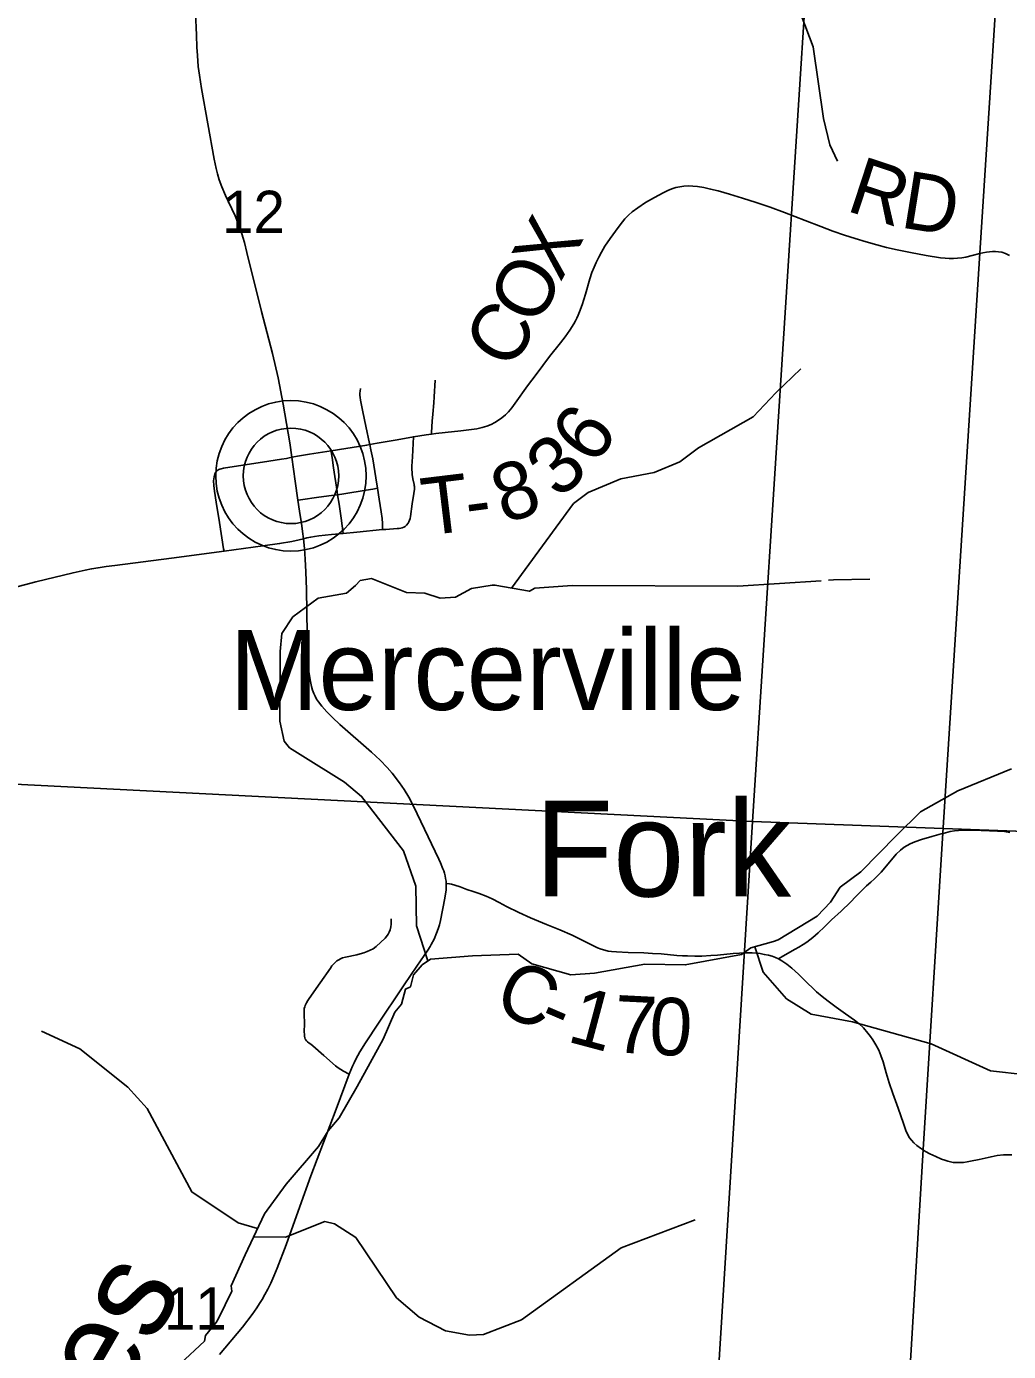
# Model space of a CAD drawing. Extents: x 0 to 34, y 0 to 22.
# Drawn here: x 27.638 to 28.609, y 18.925 to 20.235 of the extents above; entities that cross this region are included whole.
import ezdxf

# ---------------------------------------------------------------- set-up
doc = ezdxf.new("R2010")
doc.units = 0
for name, color, linetype in [('GM_X_County_Road', 7, 'Continuous'), ('GM_X_County_Road_Text', 7, 'Continuous'), ('GM_X_County_Text', 7, 'Continuous'), ('GM_X_Minor_River', 7, 'Continuous'), ('GM_X_Minor_River_Text', 7, 'Continuous'), ('GM_X_Section', 7, 'Continuous'), ('GM_X_Section_Text', 7, 'Continuous'), ('GM_X_State_Route', 7, 'Continuous'), ('GM_X_Township_Road', 7, 'Continuous'), ('GM_X_Township_Road_Text', 7, 'Continuous'), ('GM_X_Unincorporated', 7, 'Continuous'), ('GM_X_Unincorporated_Location', 7, 'Continuous'), ('GM_X_Unincorporated_Text', 7, 'Continuous')]:
    doc.layers.add(name, color=color, linetype=linetype)

msp = doc.modelspace()

# ---------------------------------------------------------------- linework, layer by layer
at = {"layer": 'GM_X_County_Road'}
for points in [[(27.5864, 19.6658), (27.5873, 19.6662), (27.5943, 19.6692), (27.6015, 19.6721), (27.6074, 19.6742), (27.613, 19.6762), (27.6189, 19.678), (27.6247, 19.6797), (27.647, 19.6855), (27.6839, 19.6946), (27.69, 19.696), (27.696, 19.6973), (27.7022, 19.6984), (27.7087, 19.6996), (27.7166, 19.7007), (27.7254, 19.7019), (27.7813, 19.7089), (27.8333, 19.7159), (27.8717, 19.7211), (27.8883, 19.7235), (27.9005, 19.7256), (27.9076, 19.727), (27.9119, 19.7281)], [(28.0531, 19.3873), (28.0564, 19.3871), (28.0584, 19.3868), (28.0615, 19.3859), (28.0668, 19.384), (28.0736, 19.3816), (28.0796, 19.3796), (28.0858, 19.3775), (28.0925, 19.375), (28.0985, 19.3723), (28.1056, 19.3686), (28.1128, 19.3648), (28.1249, 19.3588), (28.1364, 19.3534), (28.1522, 19.3469), (28.1656, 19.3415), (28.1775, 19.3363), (28.1888, 19.3309), (28.2028, 19.3237), (28.2063, 19.3224), (28.2099, 19.3214), (28.2132, 19.3207), (28.2166, 19.3203), (28.2215, 19.3198), (28.233, 19.3192), (28.2487, 19.3188), (28.2571, 19.3184), (28.2657, 19.3178), (28.2811, 19.3164), (28.2867, 19.316), (28.2917, 19.3158), (28.2991, 19.3157), (28.306, 19.3157), (28.3147, 19.3161), (28.3215, 19.3166), (28.3368, 19.3181), (28.3431, 19.3187), (28.3492, 19.3189), (28.3524, 19.319), (28.3556, 19.3188), (28.3596, 19.3185), (28.3637, 19.3181), (28.3676, 19.3174), (28.372, 19.3165), (28.3755, 19.3156), (28.3788, 19.3143), (28.3818, 19.313), (28.385, 19.3111), (28.3901, 19.3077), (28.3951, 19.3037), (28.4014, 19.2979), (28.4115, 19.2878), (28.4147, 19.2848), (28.4192, 19.2805), (28.4249, 19.2757), (28.4308, 19.2711), (28.4389, 19.2652), (28.4482, 19.2587), (28.457, 19.2525), (28.4617, 19.2486), (28.4657, 19.2448), (28.4701, 19.2396), (28.4727, 19.2363), (28.4752, 19.2328), (28.4781, 19.228), (28.481, 19.2226), (28.483, 19.2175), (28.4852, 19.2111), (28.4882, 19.2004), (28.4913, 19.1905), (28.4949, 19.1798), (28.5002, 19.1652), (28.5053, 19.1502), (28.5078, 19.1433), (28.5094, 19.1396), (28.5113, 19.1361), (28.5133, 19.1337), (28.5156, 19.1312), (28.5186, 19.1284), (28.5222, 19.1257), (28.5251, 19.1239)], [(28.5251, 19.1239), (28.5273, 19.1226), (28.5316, 19.1203), (28.5373, 19.1176), (28.543, 19.115), (28.5462, 19.1138), (28.5493, 19.1128), (28.5518, 19.1123), (28.5545, 19.1118), (28.5574, 19.1116), (28.5605, 19.1116), (28.5649, 19.1118), (28.5685, 19.1123), (28.5717, 19.1128), (28.5802, 19.1147), (28.5921, 19.1174), (28.5982, 19.1185), (28.6043, 19.1192), (28.6084, 19.1193), (28.6127, 19.1191)]]:
    msp.add_lwpolyline(points, dxfattribs=at)
at = {"layer": 'GM_X_County_Text'}
for points in [[(28.4159, 17.3358), (28.4427, 17.7695), (28.4677, 18.1732), (28.5249, 19.1245), (28.5443, 19.4375), (28.5808, 20.0106), (28.6062, 20.4055), (27.8401, 20.4449), (27.0539, 20.4845), (26.781, 20.4973), (26.0533, 20.5337), (24.4417, 20.6174), (23.8372, 20.6485), (23.8372, 14.4177)], [(29.547, 20.3639), (28.6062, 20.4055), (28.5808, 20.0106), (28.5443, 19.4375), (28.5249, 19.1245), (28.4677, 18.1732), (28.4427, 17.7695), (28.4159, 17.3358)]]:
    msp.add_lwpolyline(points, dxfattribs=at)
at = {"layer": 'GM_X_Minor_River'}
for points in [[(28.2827, 20.3892), (28.3446, 20.3542), (28.3707, 20.3061), (28.396, 20.2679), (28.4161, 20.2145), (28.4264, 20.1435), (28.4326, 20.1177), (28.4403, 20.1015)], [(28.1176, 19.6794), (28.1789, 19.763), (28.1935, 19.7739), (28.2257, 19.7873), (28.2588, 19.7938), (28.2841, 19.8044), (28.3026, 19.8182), (28.3568, 19.8488), (28.3791, 19.8724), (28.404, 19.8963)], [(28.0348, 19.311), (28.0237, 19.3457), (28.023, 19.3848), (28.0108, 19.4198), (27.9694, 19.4735), (27.9524, 19.4877), (27.9086, 19.5149), (27.8982, 19.5217), (27.8928, 19.528), (27.8885, 19.5478), (27.8887, 19.6169), (27.8903, 19.6347), (27.9014, 19.6511), (27.9265, 19.6696), (27.9543, 19.6745), (27.9632, 19.6821), (27.9679, 19.6869), (27.9793, 19.6888), (28.0137, 19.6752), (28.0318, 19.6743), (28.0471, 19.6696), (28.0623, 19.6706), (28.078, 19.6792), (28.0985, 19.6824), (28.1016, 19.6823)], [(28.4239, 19.6867), (28.3416, 19.6814), (28.1775, 19.6821), (28.1408, 19.6795), (28.1354, 19.6763), (28.1012, 19.6823)], [(28.472, 19.6883), (28.4363, 19.6875), (28.4313, 19.6872)], [(27.7898, 18.9125), (27.8139, 18.9349), (27.8151, 18.9406), (27.8256, 18.9536), (27.8279, 18.9574), (27.8411, 18.9844), (27.8403, 18.9897), (27.8543, 19.0202), (27.8732, 19.0609), (27.8947, 19.0902), (27.9268, 19.1275), (27.9362, 19.1431), (27.9472, 19.1557), (27.9649, 19.1869), (27.9906, 19.2337), (28.0023, 19.2603), (28.0087, 19.2683), (28.0128, 19.2831), (28.0177, 19.2854), (28.0208, 19.2972), (28.0272, 19.3048), (28.0294, 19.3071), (28.0374, 19.3128), (28.079, 19.316), (28.1243, 19.3176), (28.1379, 19.3081), (28.1765, 19.2972), (28.1999, 19.2988), (28.2494, 19.3076), (28.2895, 19.307), (28.3451, 19.3174), (28.3545, 19.3238), (28.3768, 19.33), (28.3814, 19.3319), (28.4199, 19.3552), (28.4331, 19.3689), (28.4429, 19.3837), (28.4633, 19.399), (28.4984, 19.4348), (28.5222, 19.4584), (28.5593, 19.479), (28.6122, 19.5008)], [(28.3582, 19.3248), (28.3667, 19.2999), (28.3896, 19.2735), (28.414, 19.2584), (28.455, 19.2506), (28.5329, 19.229), (28.5915, 19.2024), (28.6622, 19.1944), (28.696, 19.1862), (28.7089, 19.1794), (28.7219, 19.1639), (28.7437, 19.1367), (28.774, 19.0867), (28.7977, 19.0701), (28.8114, 19.0649), (28.8575, 19.0325), (28.8681, 19.0272), (28.8913, 19.0228), (28.9065, 19.0213), (28.9679, 19.0361)], [(27.8665, 19.0465), (27.8471, 19.052), (27.8014, 19.0825), (27.7572, 19.1651), (27.7381, 19.1862), (27.6908, 19.224), (27.6528, 19.2416)], [(27.8626, 19.038), (27.8942, 19.0378), (27.9329, 19.0532), (27.9427, 19.051), (27.9637, 19.0374), (28.0039, 18.978), (28.0264, 18.9588), (28.0523, 18.9452), (28.0762, 18.9408), (28.0899, 18.9416), (28.1274, 18.9562), (28.226, 19.0274), (28.2995, 19.0551)]]:
    msp.add_lwpolyline(points, dxfattribs=at)
at = {"layer": 'GM_X_Section'}
for points in [[(27.3906, 20.5203), (28.4213, 20.4653), (28.356, 19.4486), (27.3196, 19.501)], [(28.4213, 20.4653), (29.477, 20.4182), (29.4164, 19.4097), (28.356, 19.4486)], [(27.3196, 19.501), (28.356, 19.4486), (28.293, 18.4323), (27.254, 18.479)], [(28.356, 19.4486), (29.4164, 19.4097), (29.3481, 18.3713), (28.293, 18.4323)]]:
    msp.add_lwpolyline(points, close=True, dxfattribs=at)
at = {"layer": 'GM_X_State_Route'}
for points in [[(28.0457, 19.4115), (28.0278, 19.4488), (28.0206, 19.464), (28.016, 19.4728), (28.0115, 19.4803), (28.0069, 19.487), (27.9997, 19.4964), (27.9948, 19.5021), (27.9878, 19.5092), (27.9791, 19.5173), (27.9478, 19.5447), (27.9405, 19.5514), (27.9349, 19.5571), (27.93, 19.5627), (27.9266, 19.567), (27.9249, 19.5698), (27.9233, 19.5726), (27.9221, 19.5753), (27.9209, 19.5786), (27.9199, 19.5822), (27.919, 19.5856), (27.9181, 19.5909), (27.9173, 19.5971), (27.9166, 19.6063), (27.9159, 19.6212), (27.9156, 19.6342), (27.9147, 19.678), (27.9142, 19.6956), (27.9135, 19.708), (27.9128, 19.7187), (27.9119, 19.7281), (27.9109, 19.7355), (27.9098, 19.7438), (27.9084, 19.7533), (27.907, 19.7622), (27.9064, 19.7664), (27.9036, 19.7852), (27.9003, 19.8088), (27.8983, 19.8232), (27.8918, 19.8612), (27.8867, 19.8874), (27.8813, 19.9115), (27.8705, 19.953), (27.856, 20.0113), (27.8535, 20.021), (27.852, 20.0263), (27.8491, 20.0352), (27.8467, 20.0416), (27.8443, 20.0474), (27.8348, 20.0676), (27.8312, 20.0761), (27.8286, 20.0831), (27.8268, 20.0889), (27.8255, 20.0943), (27.8236, 20.1034), (27.8111, 20.1732), (27.8089, 20.1865), (27.8078, 20.195), (27.8069, 20.2061), (27.8064, 20.2143), (27.8059, 20.2262), (27.8051, 20.2485)], [(28.0371, 19.3251), (28.0382, 19.327), (28.041, 19.3324), (28.0434, 19.3382), (28.045, 19.3426), (28.0463, 19.3466), (28.0474, 19.351), (28.0518, 19.3729), (28.0525, 19.3772), (28.0529, 19.3807), (28.0531, 19.3841), (28.0531, 19.3873), (28.0529, 19.3898), (28.0525, 19.3925), (28.0521, 19.395), (28.0515, 19.3975), (28.0507, 19.3998), (28.0498, 19.4021), (28.0474, 19.4079), (28.0457, 19.4115)], [(27.8289, 18.922), (27.8515, 18.949), (27.8611, 18.9614), (27.8657, 18.9681), (27.8684, 18.9721), (27.871, 18.9763), (27.8737, 18.981), (27.8766, 18.9864), (27.8797, 18.9925), (27.8826, 18.9992), (27.886, 19.0072), (27.8947, 19.0303), (27.9084, 19.0683), (27.9193, 19.0986), (27.9442, 19.1643), (27.9572, 19.1991), (27.9588, 19.203), (27.9605, 19.2068), (27.962, 19.2102), (27.9638, 19.2138), (27.9656, 19.2173), (27.9676, 19.2209), (27.9698, 19.2246), (27.9725, 19.2289), (27.9752, 19.233), (27.984, 19.2465), (28.0115, 19.2873), (28.024, 19.3057), (28.0349, 19.3214), (28.0371, 19.3251)]]:
    msp.add_lwpolyline(points, dxfattribs=at)
at = {"layer": 'GM_X_Township_Road'}
for points in [[(27.9393, 19.815), (27.9744, 19.8209), (27.9774, 19.8214), (27.9847, 19.8227), (28.0044, 19.8261), (28.0207, 19.829), (28.0332, 19.831), (28.0385, 19.8317), (28.0429, 19.8323), (28.052, 19.8334), (28.0674, 19.835), (28.0781, 19.8362), (28.0835, 19.837), (28.0887, 19.8381), (28.0932, 19.8394), (28.0975, 19.8411), (28.1013, 19.8431), (28.1049, 19.8453), (28.1082, 19.8477), (28.1116, 19.8506), (28.1146, 19.8536), (28.1179, 19.8575), (28.1214, 19.8623), (28.1335, 19.8795), (28.142, 19.8906), (28.1554, 19.9083), (28.1661, 19.9218), (28.1709, 19.9279), (28.1754, 19.9345), (28.1792, 19.9406), (28.1809, 19.9435), (28.1824, 19.9464), (28.1837, 19.9494), (28.1849, 19.9524), (28.1875, 19.9596), (28.1908, 19.97), (28.1953, 19.9852), (28.1972, 19.9914), (28.1993, 19.9967), (28.2013, 20.0014), (28.2039, 20.0065), (28.2067, 20.0116), (28.2101, 20.0174), (28.2151, 20.0249), (28.2204, 20.0323), (28.2252, 20.0386), (28.2299, 20.0444), (28.2333, 20.048), (28.237, 20.0513), (28.2425, 20.0554), (28.2503, 20.0605), (28.259, 20.0657), (28.2678, 20.0703), (28.2723, 20.0725), (28.2762, 20.0742), (28.2802, 20.0754), (28.2842, 20.0762), (28.2881, 20.0768), (28.2924, 20.077), (28.2969, 20.0768), (28.3015, 20.0763), (28.3079, 20.0753), (28.3146, 20.0739), (28.3221, 20.0721), (28.3333, 20.0689), (28.3462, 20.065), (28.3597, 20.0607), (28.3734, 20.056), (28.3878, 20.0508), (28.408, 20.0429), (28.4235, 20.0369), (28.4356, 20.0324), (28.4471, 20.0284), (28.4577, 20.0249), (28.4684, 20.0217), (28.479, 20.0187), (28.4886, 20.0163), (28.4992, 20.0139), (28.5123, 20.0113), (28.5277, 20.0083), (28.542, 20.006), (28.5465, 20.0055), (28.5505, 20.0053), (28.5548, 20.0053), (28.5588, 20.0055), (28.5631, 20.006), (28.5671, 20.0066), (28.5734, 20.0081), (28.581, 20.0101)], [(28.581, 20.0101), (28.584, 20.0108), (28.5875, 20.0115), (28.5905, 20.012), (28.5935, 20.0123), (28.5965, 20.0123), (28.5994, 20.012), (28.6026, 20.0114), (28.6062, 20.0101), (28.6103, 20.0083)], [(28.0421, 19.8849), (28.0412, 19.8685), (28.0408, 19.8627), (28.0399, 19.8514), (28.0393, 19.8444), (28.0386, 19.8333), (28.0385, 19.8317)], [(27.9774, 19.8214), (27.9771, 19.8225), (27.9735, 19.8396), (27.9706, 19.8536), (27.9684, 19.8652), (27.968, 19.8679), (27.9677, 19.8702), (27.9677, 19.8723), (27.9678, 19.8742), (27.9683, 19.8769)], [(27.9119, 19.7281), (27.9152, 19.729), (27.919, 19.7298), (27.9229, 19.7304), (27.9271, 19.731), (27.9397, 19.7323), (27.9511, 19.7335), (27.9645, 19.7348), (27.99, 19.7373), (27.9902, 19.7403), (27.9901, 19.7434), (27.9897, 19.7481), (27.9888, 19.7547), (27.9868, 19.7674), (27.9851, 19.7781), (27.9836, 19.7883), (27.9804, 19.8071), (27.9785, 19.816), (27.9774, 19.8214)], [(27.99, 19.7373), (27.9933, 19.7375), (28.0047, 19.7383), (28.0066, 19.7384), (28.0082, 19.7387), (28.0096, 19.7391), (28.0111, 19.7397), (28.0123, 19.7405), (28.0138, 19.7418), (28.0153, 19.7437), (28.0161, 19.7449), (28.0169, 19.7465), (28.0175, 19.7482), (28.0179, 19.7502), (28.0194, 19.7626), (28.021, 19.7731), (28.0216, 19.7772), (28.0217, 19.7784), (28.0217, 19.7798), (28.0215, 19.7809), (28.0213, 19.782), (28.0202, 19.7873), (28.0195, 19.7916), (28.0193, 19.794), (28.0192, 19.7965), (28.0192, 19.8), (28.0198, 19.8093), (28.0207, 19.829)], [(27.8282, 19.7966), (27.8291, 19.797), (27.8304, 19.7974), (27.8328, 19.7981), (27.8348, 19.7985), (27.8715, 19.8041), (27.89, 19.8068), (27.8951, 19.8077), (27.9003, 19.8088)], [(27.9003, 19.8088), (27.908, 19.8102), (27.9177, 19.8118), (27.9393, 19.815)], [(27.9511, 19.7335), (27.9493, 19.7485), (27.9472, 19.7623), (27.9456, 19.7718), (27.9451, 19.775), (27.9417, 19.7982), (27.9403, 19.8086), (27.9394, 19.8141), (27.9393, 19.815)], [(27.8333, 19.7159), (27.8329, 19.7183), (27.8289, 19.7444), (27.8256, 19.7644), (27.8239, 19.7752), (27.8231, 19.781), (27.8229, 19.7854), (27.8234, 19.7893), (27.8243, 19.7924), (27.8253, 19.7942), (27.8262, 19.7953), (27.8273, 19.7961), (27.8282, 19.7966)], [(27.9064, 19.7664), (27.9089, 19.7667), (27.9272, 19.7692), (27.9395, 19.7709), (27.9456, 19.7718), (27.9518, 19.7727), (27.9739, 19.7764), (27.9806, 19.7774), (27.9851, 19.7781)], [(28.5445, 19.4369), (28.5516, 19.4387), (28.556, 19.4395), (28.5599, 19.4399), (28.5634, 19.44), (28.568, 19.44), (28.5824, 19.4397), (28.5984, 19.4392), (28.6052, 19.4387), (28.6107, 19.438)], [(28.3818, 19.313), (28.3862, 19.3155), (28.3982, 19.3224), (28.402, 19.3245), (28.4063, 19.3271), (28.4099, 19.3295), (28.4158, 19.334), (28.4209, 19.3386), (28.4272, 19.3446), (28.4312, 19.3485), (28.4343, 19.3514), (28.4438, 19.3602), (28.4531, 19.3691), (28.4582, 19.3745), (28.463, 19.3793), (28.4665, 19.3829), (28.4688, 19.385), (28.4731, 19.3886), (28.4766, 19.3919), (28.4806, 19.396), (28.4832, 19.3986), (28.4936, 19.4107), (28.4982, 19.4163), (28.5024, 19.4204), (28.5061, 19.4234), (28.5089, 19.4251), (28.5121, 19.4266), (28.5168, 19.4285), (28.5231, 19.4308), (28.5333, 19.434), (28.5428, 19.4365), (28.5445, 19.4369)], [(27.9572, 19.1991), (27.9515, 19.2019), (27.9487, 19.2036), (27.9462, 19.2053), (27.9437, 19.2073), (27.932, 19.2175), (27.921, 19.227), (27.9191, 19.2285), (27.9174, 19.2297), (27.916, 19.2308), (27.9149, 19.2319), (27.9142, 19.2328), (27.9137, 19.2336), (27.9132, 19.235), (27.9129, 19.2365), (27.9128, 19.2385), (27.9127, 19.2405), (27.9128, 19.2492), (27.9124, 19.2582), (27.9124, 19.2603), (27.9125, 19.2622), (27.9127, 19.264), (27.9131, 19.2655), (27.9137, 19.267), (27.9149, 19.2696), (27.9162, 19.2717), (27.9176, 19.2738), (27.9283, 19.2894), (27.9385, 19.3038), (27.94, 19.3059), (27.9415, 19.3077), (27.9433, 19.3095), (27.945, 19.311), (27.9467, 19.3121), (27.9484, 19.313), (27.9504, 19.3138), (27.9535, 19.3146), (27.9646, 19.317), (27.9678, 19.3178), (27.9717, 19.3189), (27.975, 19.3201), (27.978, 19.3214), (27.9809, 19.323), (27.9838, 19.3252), (27.9927, 19.3333), (27.9941, 19.3351), (27.9956, 19.3372), (27.9966, 19.3392), (27.9975, 19.3416), (27.9982, 19.3445), (27.9986, 19.3472), (27.9987, 19.3499), (27.9987, 19.3525)]]:
    msp.add_lwpolyline(points, dxfattribs=at)
at = {"layer": 'GM_X_Unincorporated'}
for radius in [0.0744, 0.0472]:
    msp.add_circle((27.8995, 19.7904), radius, dxfattribs=at)
at = {"layer": 'GM_X_Unincorporated_Location'}
msp.add_line((27.8995, 19.7904), (27.8995, 19.7904), dxfattribs=at)

# ---------------------------------------------------------------- texts
at = {"layer": 'GM_X_County_Road_Text'}
for s, rotation, p in [('C', 336.0016, (28.0978, 19.263)), ('1', 345.0845, (28.1712, 19.2316)), ('7', 357.1207, (28.2179, 19.2206)), ('0', 356.7979, (28.2527, 19.2188)), ('-', 336.7539, (28.1412, 19.2437))]:
    msp.add_text(s, height=0.0568, rotation=rotation, dxfattribs=at).set_placement(p)
at = {"layer": 'GM_X_Minor_River_Text'}
for s, height, rotation, p in [('Fork', 0.0947, 359.9962, (28.1408, 19.3746)), ('Drakes', 0.09469, 59.9948, (27.5929, 18.6388))]:
    msp.add_text(s, height=height, rotation=rotation, dxfattribs=at).set_placement(p)
at = {"layer": 'GM_X_Section_Text'}
for s, p in [('12', (27.8313, 20.0304)), ('11', (27.7738, 18.9463))]:
    msp.add_text(s, height=0.04186, rotation=0, dxfattribs=at).set_placement(p)
at = {"layer": 'GM_X_Township_Road_Text'}
for s, rotation, p in [('R', 341.8292, (28.4474, 20.053)), ('D', 350.8483, (28.5011, 20.0362)), ('X', 62.0664, (28.1661, 19.9811)), ('O', 62.6275, (28.1432, 19.9368)), ('C', 57.9501, (28.1159, 19.8929)), ('6', 53.6809, (28.1991, 19.7991)), ('3', 41.9178, (28.1645, 19.7664)), ('8', 19.4828, (28.1108, 19.7424)), ('T', 6.8885, (28.0322, 19.7312)), ('-', 7.4441, (28.075, 19.7363))]:
    msp.add_text(s, height=0.0568, rotation=rotation, dxfattribs=at).set_placement(p)
at = {"layer": 'GM_X_Unincorporated_Text'}
msp.add_text('Mercerville', height=0.078977, rotation=0, dxfattribs=at).set_placement((27.8388, 19.559))

doc.saveas('drawing.dxf')
